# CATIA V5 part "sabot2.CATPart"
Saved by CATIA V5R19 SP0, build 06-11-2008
Part number: sabot2
Bounding box of the stored display mesh (mm): x -312.443 to -90.052, y 208.914 to 579.923, z -30 to 30
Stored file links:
  C:\Users\Thibaud\Desktop\IFMA\thinkmotion\IAO\modele_catia\sabot2.CATPart
  C:\Users\Thibaud\Desktop\IFMA\thinkmotion\IAO\modele_catia\sabot1.CATPart
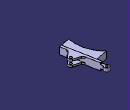
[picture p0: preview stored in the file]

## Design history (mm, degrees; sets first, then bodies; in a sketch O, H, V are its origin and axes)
Body1 (main body)
  Plane1: stored without definition
  Line1 "axe_pivot_sabot2_batit": stored without definition
  Line2: stored without definition
  Plane2: stored without definition
  Sketch1 on Plane1, origin (0, 0, 0), H (1, 0, 0), V (0, 1, 0)
    point P1 (-207.4461, 520.7197)
    line L1 (-207.4461, 520.7197) -> (-197.626, 522.6082)
    line L2 (-197.626, 522.6082) -> (-140.9718, 228.0063)
    line L3 (-140.9718, 228.0063) -> (-150.7919, 226.1178)
    point P2 (-197.626, 522.6082)
    point P3 (-140.9718, 228.0063)
    point P4 (-150.7919, 226.1178)
    axis line L4 (-207.4461, 520.7197) -> (-150.7919, 226.1178)
    reference projected point E1 (-215, 560) from Line1
    reference projected line E2 (-240, 330) -> (-110, 355) from Line2
    point P5 (-160.612, 224.2293)
    point P6 (-217.2662, 518.8313)
    line L5 (-217.2662, 518.8313) -> (-160.612, 224.2293)
    point P7 (-150.7919, 226.1178)
    line L6 (-160.612, 224.2293) -> (-150.7919, 226.1178)
    point P8 (-207.4461, 520.7197)
    line L7 (-207.4461, 520.7197) -> (-217.2662, 518.8313)
    reference projected point E3 (-215, 560) from Line11
    length L1 = 10
    length L2 = 300
    distance L1 E3 = 40
    perpendicularity: L2 L1, L2 L3, L4 L1, L4 E2
    coincidence: L4 E1, P1 P8, P4 P7
    symmetry: P3 P5 L4, P2 P6 L4, L2 L5 L4, P4 P7 L4, L3 L6 L4, P1 P8 L4, L1 L7 L4
  Pad1: profile Sketch1, direction (0, 0, 1), length 30, mirrored extent
  Line3 "lineaire_rect_sabot2_roue2": stored without definition
  Plane3: stored without definition
  Sketch2 on Plane2, origin (0, 0, 0), H (1, 0, 0), V (0, 1, 0)
    arc A1 centre (-500, 270) radius 266.8333 from (-240.2531, 208.9137) to (-312.4426, 459.7952) ccw
    point P1 (-500, 270)
    reference projected point E1 (-240, 330) from Line3
    line L1 (-160.612, 224.2293) -> (-240.2531, 208.9137)
    line L2 (-312.4426, 459.7952) -> (-209.7123, 479.551)
    line L3 (-209.7123, 479.551) -> (-160.612, 224.2293)
    reference projected line E2 (-160.612, 224.2293) -> (-150.7919, 226.1178) from edge [face of Pad1 from Sketch1.L6 | end face of Pad1]
    reference projected line E3 (-217.2662, 518.8313) -> (-160.612, 224.2293) from edge [face of Pad1 from Sketch1.L5 | end face of Pad1]
    distance P1 V = 500
    distance P1 H = 270
    length L3 = 260
    coincidence: A1 E1, L1 E2, E3 L3
    perpendicularity: L3 L2, L3 L1
  Pad2: profile Sketch2, direction (0, 0, 1), length 29, mirrored extent
  Line4 "axe_pivot_sabot2_batit": stored without definition
  Plane4: stored without definition
  Sketch3 on Plane3, origin (0, 0, 0), H (1, 0, 0), V (0, 1, 0)
    arc A1 centre (-215, 560) radius 20 from (-200.1944, 546.5541) to (-223.7625, 542.0217) ccw
    point P1 (-215, 560)
    reference projected point E1 (-215, 560) from Line4
    circle A2 centre (-215, 560) radius 10
    line L1 (-201.403, 542.2483) -> (-197.626, 522.6082)
    line L2 (-197.626, 522.6082) -> (-217.2662, 518.8313)
    line L3 (-217.2662, 518.8313) -> (-221.0431, 538.4714)
    reference projected line E2 (-197.626, 522.6082) -> (-207.4461, 520.7197) from edge [face of Pad1 from Sketch1.L1 | end face of Pad1]
    reference projected line E3 (-140.9718, 228.0063) -> (-197.626, 522.6082) from edge [face of Pad1 from Sketch1.L2 | end face of Pad1]
    reference projected line E4 (-217.2662, 518.8313) -> (-160.612, 224.2293) from edge [face of Pad1 from Sketch1.L5 | end face of Pad1]
    arc A3 centre (-196.493, 543.1926) radius 5 from (-200.1944, 546.5541) to (-201.403, 542.2483) ccw
    point P7 (-221.5491, 541.1027)
    arc A4 centre (-225.9531, 537.5272) radius 5 from (-223.7625, 542.0217) to (-221.0431, 538.4714) cw
    radius A1 = 20
    radius A2 = 10
    radius A3 = 5
    radius A4 = 5
    coincidence: P1 E1, L2 E2, L1 E3, L3 E4, P7 L3, A1 P7
    concentricity: A2 A1
    perpendicularity: L2 L1
    parallelism: L1 L3
    tangency: A3 A1, A3 L1, A4 L3, A4 A1
  Pad3: profile Sketch3, direction (0, 0, 1), length 15, mirrored extent
  Line5 "axe_pivot_sabot2_bielette3": stored without definition
  Line6 to Line9: stored without definition
  Line10 "axe_pivot_sabot2_bielette3": stored without definition
  Sketch4 on end face of Pad1, origin (0, 0, 30), H (1, 0, 0), V (0, 1, 0)
    point P1 (-110, 355)
    arc A1 centre (-110, 355) radius 20 from (-96.909, 339.8796) to (-103.4509, 373.8973) ccw
    circle A2 centre (-110, 355) radius 10
    line L1 (-103.4509, 373.8973) -> (-162.8, 394.4656)
    line L2 (-96.909, 339.8796) -> (-144.3962, 298.7659)
    point P2 (-178.9582, 400.0654)
    arc A3 centre (-156.2509, 413.3629) radius 20 from (-162.8, 394.4656) to (-175.891, 409.586) cw
    arc A4 centre (-131.3052, 283.6455) radius 20 from (-144.3962, 298.7659) to (-150.9453, 279.8686) ccw
    line L3 (-150.9453, 279.8686) -> (-175.891, 409.586)
    point P3 (-175.891, 409.586)
    point P6 (-175.891, 409.586)
    reference projected line E1 (-240, 330) -> (-110, 355) from Line8
    reference projected line E2 (-240, 330) -> (-110, 355) from Line9
    reference projected point E3 (-110, 355) from Line10
    reference projected line E4 (-140.9718, 228.0063) -> (-197.626, 522.6082) from edge [face of Pad1 from Sketch1.L2 | end face of Pad1]
    radius A1 = 20
    radius A2 = 10
    radius A3 = 20
    radius A4 = 20
    angle E1 L1 = 30
    angle L2 E2 = 30 {= Sketch4.angle(E1 L1)}
    tangency: L1 A1, L2 A1, A3 L1, A4 L2, L3 A3, L3 A4
    coincidence: L1 P2, P3 A3, P1 E3, L3 E4, P6 P3
    concentricity: A1 A2
  Pad4: profile Sketch4, direction (0, 0, -1), length 15
  RectPattern1: of Pad4, direction 1 instances 2, spacing 45, along edge [face of Pad1 from Sketch1.L2 | face of Pad1 from Sketch1.L3] reversed
  Line11 "axe_pivot_sabot2_batit": stored without definition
